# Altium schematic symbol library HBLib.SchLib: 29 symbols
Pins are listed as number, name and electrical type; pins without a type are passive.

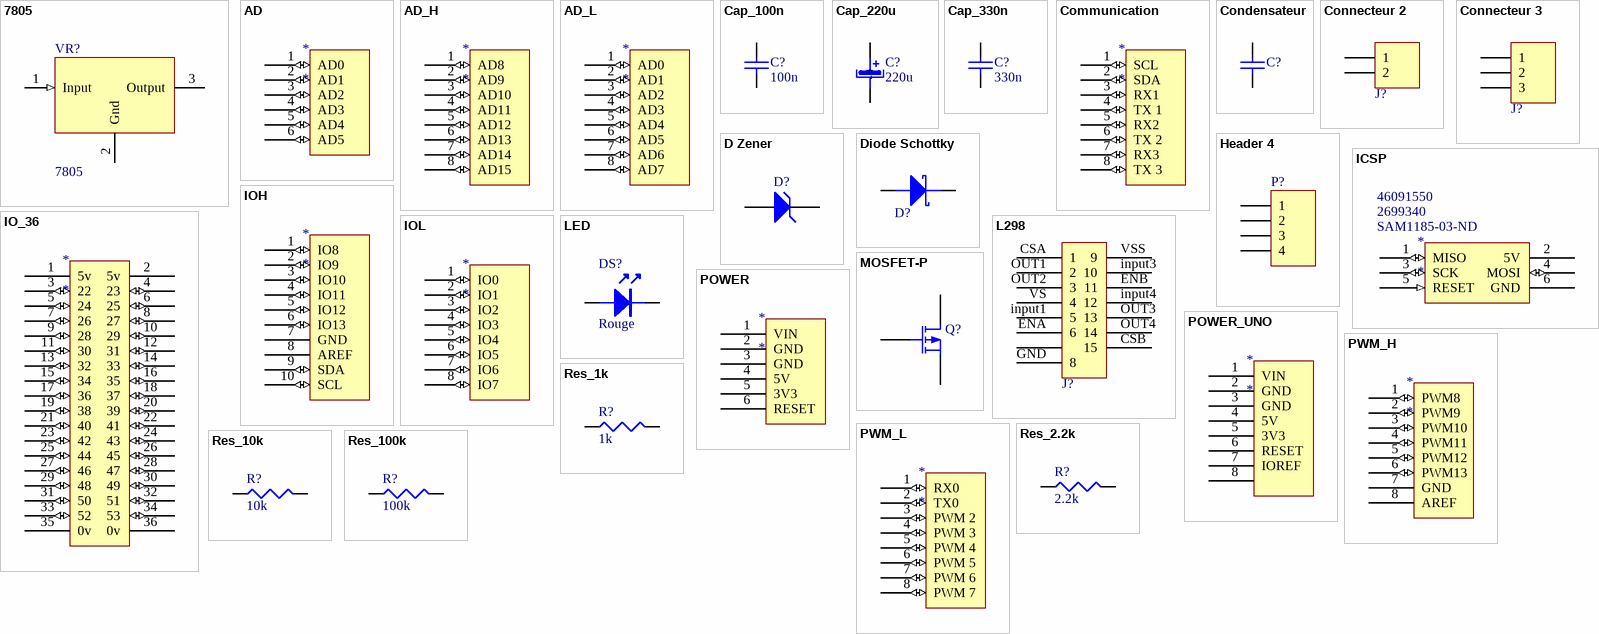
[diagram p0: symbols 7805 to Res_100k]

## 7805
designator VR?  Type: 7805
Régulateur 5V
footprint TO252
footprint TO-220AB (TO, Thru-Hole, Vertical, Heatsink Mounted; 3 In-Line Leads; Pitch 2.54 mm)
pins: 1 Input (in), 2 Gnd (power), 3 Output (power)

## AD
designator *
Header, 6-Pin
footprint Header 6x1 8.5mm (Stackable 6 pin header)
pins: 1 AD0 (io), 2 AD1 (io), 3 AD2 (io), 4 AD3 (io), 5 AD4 (io), 6 AD5 (io)

## AD_H
designator *
Header, 8-Pin
footprint Header 8x1 8.5mm (Stackable 8 pin header)
pins: 1 AD8 (io), 2 AD9 (io), 3 AD10 (io), 4 AD11 (io), 5 AD12 (io), 6 AD13 (io), 7 AD14 (io), 8 AD15 (io)

## AD_L
designator *
Header, 8-Pin
footprint Header 8x1 8.5mm (Stackable 8 pin header)
pins: 1 AD0 (io), 2 AD1 (io), 3 AD2 (io), 4 AD3 (io), 5 AD4 (io), 6 AD5 (io), 7 AD6 (io), 8 AD7 (io)

## Cap_100n
designator C?  value 100n
Condensateur
footprint C1206 (Chip Capacitor, Body 3.2x1.6mm, IPC High Density)
footprint Model Name (Model Description)
pins: 1, 2

## Cap_220u
designator C?  value 220u
Condensateur polatisé; Type: Condensateur polarisé debout
footprint CAPAE0810X700N
pins: NEG -, POS +
2 alternate drawings of the same symbol

## Cap_330n
designator C?  value 330n
Condensateur
footprint C1206 (Chip Capacitor, Body 3.2x1.6mm, IPC High Density)
footprint Model Name (Model Description)
pins: 1, 2

## Communication
designator *
Header, 8-Pin
footprint Header 8x1 8.5mm (Stackable 8 pin header)
pins: 1 SCL (io), 2 SDA (io), 3 RX1 (io), 4 TX 1 (io), 5 RX2 (io), 6 TX 2 (io), 7 RX3 (io), 8 TX 3 (io)

## Condensateur
designator C?
Condensateur
footprint C1206 (Chip Capacitor, Body 3.2x1.6mm, IPC High Density)
footprint Model Name (Model Description)
pins: 1, 2

## Connecteur 2
designator J?
Connecteur
footprint Header_2
footprint Header_2Ecam
pins: 1, 2

## Connecteur 3
designator J?
Connecteur
footprint CONVIS-3 (Connecteur à vis 3 contacts Pitch 5.08)
footprint HDR1X3 (Connector; Header; 3 Position)
pins: 1, 2, 3

## D Zener
designator D?
Zener Diode
footprint SOD-123
pins: 1 K, 2 A

## Diode Schottky
designator D?
Diode Schottky
footprint SOD-123
pins: 1 K, 2 A

## Header 4
designator P?
Header, 4-Pin
footprint MOLEX_22-27-2081
footprint Header4_ecam
pins: 1, 2, 3, 4

## ICSP
designator *  Supplier Part Number 1: SAM1185-03-ND  Supplier Part Number 2: 2699340  Supplier Part Number 3: 46091550
footprint ICSP
pins: 1 MISO (io), 2 5V (power), 3 SCK (io), 4 MOSI (io), 5 RESET (in), 6 GND (power)

## IO_36
designator *
Header, 36-Pin
footprint HEADER 36X 8MM (Stackable 10 pin header)
pins: 1 5v (power), 2 5v (power), 3 22 (io) "Digital 22", 4 23 (io) "Digital 23", 5 24 (io) "Digital 24", 6 25 (io) "Digital 25", 7 26 (io) "Digital 26", 8 27 (io) "Digital 27", 9 28 (io) "Digital 28", 10 29 (io) "Digital 29", 11 30 (io) "Digital 30", 12 31 (io) "Digital 31", 13 32 (io) "Digital 32", 14 33 (io) "Digital 33", 15 34 (io) "Digital 34", 16 35 (io) "Digital 35", 17 36 (io) "Digital 36", 18 37 (io) "Digital 37", 19 38 (io) "Digital 38", 20 39 (io) "Digital 39", 21 40 (io) "Digital 40", 22 41 (io) "Digital 41", 23 42 (io) "Digital 42", 24 43 (io) "Digital 43", 25 44 (io) "Digital 44", 26 45 (io) "Digital 45", 27 46 (io) "Digital 46", 28 47 (io) "Digital 47", 29 48 (io) "Digital 48", 30 49 (io) "Digital 49", 31 50 (io) "Digital 50", 32 51 (io) "Digital 51", 33 52 (io) "Digital 52", 34 53 (io) "Digital 53", 35 0v (power), 36 0v (power)

## IOH
designator *
Header, 10-Pin
footprint Header 10x1 8.5mm (Stackable 10 pin header)
pins: 1 IO8 (io), 2 IO9 (io), 3 IO10 (io), 4 IO11 (io), 5 IO12 (io), 6 IO13 (io), 7 GND (power), 8 AREF, 9 SDA (io), 10 SCL (io)

## IOL
designator *
Header, 8-Pin
footprint Header 8x1 8.5mm (Stackable 8 pin header)
pins: 1 IO0 (io), 2 IO1 (io), 3 IO2 (io), 4 IO3 (io), 5 IO4 (io), 6 IO5 (io), 7 IO6 (io), 8 IO7 (io)

## L298
designator J?
Connecteur
footprint MultiWatt15 (MultiWatt15; 15 Leads; Row Spacing 5.08 mm; Pitch 2.54 mm)
pins: CSA 1, CSB 15, ENA 6, ENB 11, GND 8, input1 5, input2 7, input3 10, input4 12, OUT1 2, OUT2 3, OUT3 13, OUT4 14, VS 4, VSS 9

## LED
designator DS?  Color: Rouge
LED
footprint 3.5X2.8X1.9 (SM LED; 2 C-Bend Leads; Body 3.5 x 2.8 x 1.9 mm, inc leads (LxWxH typ))
pins: 1 A, 2 K

## MOSFET-P
designator Q?
P-Channel MOSFET
footprint TO-220-AB (TO, Thru-Hole, Vertical, Heatsink Mounted; 3 In-Line Leads; Pitch 2.54 mm)
pins: D, G, S

## POWER
designator *
Header, 6-Pin
footprint Header 6x1 8.5mm (Stackable 6 pin header)
pins: 1 VIN (power), 2 GND (power), 3 GND (power), 4 5V (power), 5 3V3 (power), 6 RESET

## POWER_UNO
designator *
Header, 8-Pin
footprint Header 8x1 8.5mm (Stackable 8 pin header)
pins: 1 VIN (power), 2 GND (power), 3 GND (power), 4 5V (power), 5 3V3 (power), 6 RESET, 7 IOREF (power), 8

## PWM_H
designator *
Header, 8-Pin
footprint Header 8x1 8.5mm (Stackable 8 pin header)
pins: 1 PWM8 (io) "PWM 8", 2 PWM9 (io) "PWM 9", 3 PWM10 (io) "PWM 10", 4 PWM11 (io) "PWM 11", 5 PWM12 (io) "PWM 12", 6 PWM13 (io) "PWM 13", 7 GND (power), 8 AREF

## PWM_L
designator *
Header, 8-Pin
footprint Header 8x1 8.5mm (Stackable 8 pin header)
pins: 1 RX0 (io) "PWM 0 & RX0", 2 TX0 (io) "PWM 1 & TX0", 3 PWM 2 (io), 4 PWM 3 (io), 5 PWM 4 (io), 6 PWM 5 (io), 7 PWM 6 (io), 8 PWM 7 (io)

## Res_1k
designator R?  value 1k
Résistance standard
footprint 6-0805_L (Chip Resistor, Body 2.0x1.2mm, IPC High Density)
footprint J1-0603 (Chip Resistor, Body 1.6x0.8mm, IPC High Density)
pins: 1, 2
3 alternate drawings of the same symbol

## Res_2.2k
designator R?  value 2.2k
Résistance standard
footprint 6-0805_L (Chip Resistor, Body 2.0x1.2mm, IPC High Density)
pins: 1, 2
3 alternate drawings of the same symbol

## Res_10k
designator R?  value 10k
Résistance standard
footprint 6-0805_L (Chip Resistor, Body 2.0x1.2mm, IPC High Density)
footprint J1-0603 (Chip Resistor, Body 1.6x0.8mm, IPC High Density)
pins: 1, 2
3 alternate drawings of the same symbol

## Res_100k
designator R?  value 100k
Résistance standard
footprint 6-0805_L (Chip Resistor, Body 2.0x1.2mm, IPC High Density)
footprint J1-0603 (Chip Resistor, Body 1.6x0.8mm, IPC High Density)
pins: 1, 2
3 alternate drawings of the same symbol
